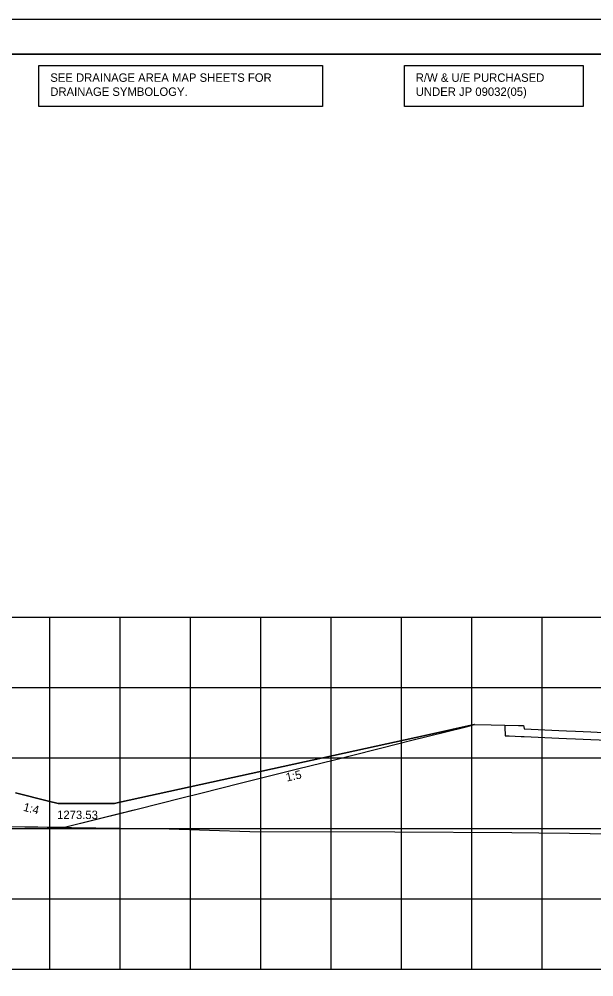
# Model space of a CAD drawing. Extents: x 2148105 to 2149976, y 144169 to 149705.
# Drawn here: x 2148429 to 2148510.7, y 148600.8 to 148736.9 of the extents above; entities that cross this region are included whole.
import ezdxf

# ---------------------------------------------------------------- set-up
doc = ezdxf.new("R2010")
doc.units = 0
for name, color, linetype in [('INR_Tracking', 7, 'Continuous'), ('PH1a-2-RampC', 7, 'Continuous'), ('PH1a-PR-DividingStrip', 7, 'Continuous'), ('PH1a-PR-ServRd', 7, 'Continuous'), ('PR-ApproachSlab', 7, 'Continuous'), ('PR-SHLDR-RMP-H', 7, 'Continuous'), ('PR_Align_Ramp_J', 7, 'Continuous'), ('PR_Storm_Conc_Box_PH1B', 7, 'Continuous'), ('PR_Storm_Conc_Pipe_PH1B', 7, 'Continuous'), ('PR_Storm_Inlet_CICI_PH1B', 7, 'Continuous'), ('PR_Storm_MH', 7, 'Continuous'), ('PR_Storm_Standard_Median_Drain_PH1B', 7, 'Continuous'), ('TopCut', 7, 'Continuous')]:
    doc.layers.add(name, color=color, linetype=linetype)

msp = doc.modelspace()

# ---------------------------------------------------------------- linework, layer by layer
at = {"layer": 'INR_Tracking'}
msp.add_lwpolyline([(2148428.47, 148626.94), (2148433.15, 148625.77), (2148434.5, 148625.43), (2148434.52, 148625.43), (2148442.5, 148625.43), (2148443.08, 148625.56), (2148486.88, 148635.16), (2148493.66, 148636.65), (2148493.67, 148636.65)], dxfattribs=at)
at = {"layer": 'PH1a-PR-ServRd'}
msp.add_lwpolyline([(2148570.82, 148521.91), (2148255.82, 148521.91), (2148255.82, 148731.91), (2148570.82, 148731.91)], close=True, dxfattribs=at)
at = {"layer": 'PR-ApproachSlab'}
msp.add_lwpolyline([(2148435.41, 148622.06), (2148443.85, 148624.17), (2148445.12, 148624.49), (2148445.74, 148624.65), (2148452.11, 148626.24), (2148454.81, 148626.92), (2148460.37, 148628.31), (2148464.37, 148629.31), (2148468.54, 148630.35), (2148473.8, 148631.67), (2148476.61, 148632.38), (2148483.12, 148634.01), (2148484.61, 148634.38), (2148492.32, 148636.31), (2148492.51, 148636.36), (2148493.67, 148636.65), (2148496.05, 148636.61), (2148497.99, 148636.57), (2148499.95, 148636.54), (2148500.05, 148636.54), (2148500.06, 148636.54), (2148500.06, 148636.54), (2148500.08, 148636.54), (2148500.33, 148636.54), (2148500.65, 148636.54), (2148500.73, 148636.08), (2148500.73, 148636.04), (2148500.73, 148636.04), (2148500.73, 148636.04), (2148505.67, 148635.82), (2148506.77, 148635.77), (2148508.07, 148635.72), (2148510.21, 148635.62), (2148513.84, 148635.46)], dxfattribs=at)
at = {"layer": 'PR-SHLDR-RMP-H'}
msp.add_lwpolyline([(2148435.41, 148622.06), (2148443.76, 148624.15), (2148443.85, 148624.17), (2148444.41, 148624.31), (2148445.74, 148624.65), (2148452.11, 148626.24), (2148454.81, 148626.92), (2148460.37, 148628.31), (2148464.37, 148629.31), (2148468.54, 148630.35), (2148473.8, 148631.67), (2148476.61, 148632.38), (2148483.12, 148634.01), (2148484.61, 148634.38), (2148492.32, 148636.31), (2148492.51, 148636.36), (2148493.67, 148636.65), (2148496.05, 148636.61), (2148497.99, 148636.57), (2148498, 148636.34), (2148498, 148636.24), (2148498.01, 148636.24), (2148498.01, 148636.24), (2148498.02, 148635.99), (2148498.04, 148635.41), (2148498.05, 148635.17), (2148498.05, 148635.07), (2148498.63, 148635.05), (2148500.33, 148634.97), (2148500.73, 148634.96), (2148500.73, 148634.96), (2148500.73, 148634.96), (2148505.67, 148634.74), (2148506.77, 148634.69), (2148508.07, 148634.63), (2148510.21, 148634.54), (2148513.84, 148634.38)], dxfattribs=at)
at = {"layer": 'PR_Align_Ramp_J'}
msp.add_lwpolyline([(2148236.32, 148736.91), (2148576.32, 148736.91), (2148576.32, 148516.91), (2148236.32, 148516.91)], close=True, dxfattribs=at)
at = {"layer": 'PR_Storm_Conc_Box_PH1B'}
for p, q in [((2148263.32, 148651.91), (2148563.32, 148651.91)), ((2148433.32, 148601.91), (2148433.32, 148651.91)), ((2148443.32, 148601.91), (2148443.32, 148651.91)), ((2148453.32, 148601.91), (2148453.32, 148651.91)), ((2148463.32, 148601.91), (2148463.32, 148651.91)), ((2148473.32, 148601.91), (2148473.32, 148651.91)), ((2148483.32, 148601.91), (2148483.32, 148651.91)), ((2148493.32, 148601.91), (2148493.32, 148651.91)), ((2148503.32, 148601.91), (2148503.32, 148651.91)), ((2148263.32, 148641.91), (2148563.32, 148641.91)), ((2148263.32, 148631.91), (2148563.32, 148631.91)), ((2148263.32, 148621.91), (2148563.32, 148621.91)), ((2148263.32, 148611.91), (2148563.32, 148611.91)), ((2148263.32, 148601.91), (2148563.32, 148601.91))]:
    msp.add_line(p, q, dxfattribs=at)
at = {"layer": 'PR_Storm_Conc_Pipe_PH1B'}
msp.add_lwpolyline([(2148255.82, 148521.91), (2148570.82, 148521.91), (2148570.82, 148731.91), (2148255.82, 148731.91)], close=True, dxfattribs=at)
msp.add_lwpolyline([(2148255.82, 148521.91), (2148570.82, 148521.91), (2148570.82, 148731.91), (2148255.82, 148731.91)], close=True, dxfattribs=at)
at = {"layer": 'PR_Storm_Inlet_CICI_PH1B'}
msp.add_lwpolyline([(2148400.99, 148622.56), (2148432.93, 148622.09), (2148450.27, 148621.86), (2148461.76, 148621.46), (2148482.36, 148621.43), (2148498.99, 148621.3), (2148502.83, 148621.26), (2148507.2, 148621.22), (2148510.14, 148621.2), (2148516.03, 148621.11), (2148519.25, 148621.12), (2148525.8, 148621.07), (2148527.21, 148621.07), (2148527.23, 148621.08), (2148527.63, 148621.04), (2148532.17, 148620.93), (2148546.49, 148620.59), (2148547.86, 148620.54), (2148559.86, 148620.57), (2148563.32, 148620.6)], dxfattribs=at)
at = {"layer": 'PR_Storm_MH'}
for points in [[(2148431.78, 148730.34), (2148472.07, 148730.34), (2148472.07, 148724.47), (2148431.78, 148724.47)], [(2148483.72, 148730.34), (2148509.15, 148730.34), (2148509.15, 148724.47), (2148483.72, 148724.47)]]:
    msp.add_lwpolyline(points, close=True, dxfattribs=at)
at = {"layer": 'PR_Storm_Standard_Median_Drain_PH1B'}
msp.add_line((2148263.32, 148601.91), (2148563.32, 148601.91), dxfattribs=at)
at = {"layer": 'TopCut'}
msp.add_lwpolyline([(2148427.86, 148622.17), (2148435.41, 148622.06), (2148443.76, 148624.15), (2148443.85, 148624.17), (2148444.41, 148624.31), (2148445.74, 148624.65), (2148452.11, 148626.24), (2148454.81, 148626.92), (2148460.37, 148628.31), (2148464.37, 148629.31), (2148468.54, 148630.35), (2148473.8, 148631.67), (2148476.61, 148632.38), (2148483.12, 148634.01), (2148484.61, 148634.38), (2148492.32, 148636.31), (2148492.51, 148636.36), (2148493.67, 148636.65), (2148493.66, 148636.65), (2148486.88, 148635.16), (2148443.08, 148625.56), (2148442.5, 148625.43), (2148434.52, 148625.43), (2148434.5, 148625.43), (2148433.15, 148625.77), (2148428.47, 148626.94)], dxfattribs=at)

# ---------------------------------------------------------------- texts
at = {"layer": 'PH1a-2-RampC'}
msp.add_text('1273.53', height=1.2, dxfattribs=at).set_placement((2148434.36, 148623.23))
at = {"layer": 'PH1a-PR-DividingStrip'}
for s, rotation, p in [('1:5', 12.3615, (2148467.02, 148628.55)), ('1:4', 345.9652, (2148429.47, 148624.42))]:
    msp.add_text(s, height=1.2, rotation=rotation, dxfattribs=at).set_placement(p)
at = {"layer": 'PR_Storm_MH'}
for s, p in [('SEE DRAINAGE AREA MAP SHEETS FOR', (2148433.39, 148728)), ('R/W & U/E PURCHASED', (2148485.34, 148728)), ('DRAINAGE SYMBOLOGY.', (2148433.39, 148726)), ('UNDER JP 09032(05)', (2148485.34, 148726))]:
    msp.add_text(s, height=1.2, dxfattribs=at).set_placement(p)

doc.saveas('drawing.dxf')
